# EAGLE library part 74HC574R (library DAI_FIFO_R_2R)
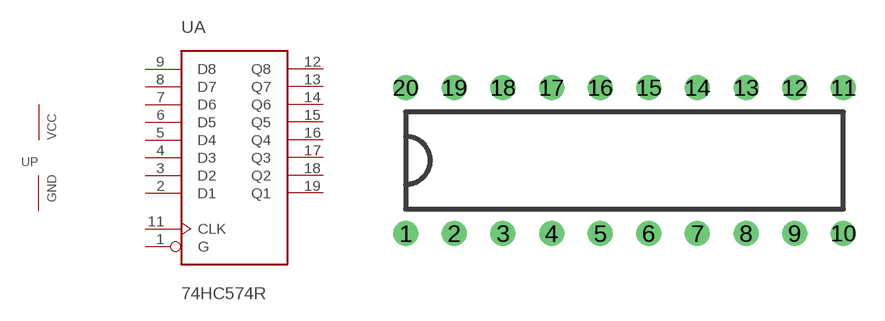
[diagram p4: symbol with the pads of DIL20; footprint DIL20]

Designator prefix U; gates P=DIP20_PWR A=74HC574R

## 74HC574R  [DIL20]
1  A:G  in
2  A:D1  in
3  A:D2  in
4  A:D3  in
5  A:D4  in
6  A:D5  in
7  A:D6  in
8  A:D7  in
9  A:D8  in
10  P:GND  pwr
11  A:CLK  in
12  A:Q8  hiz
13  A:Q7  hiz
14  A:Q6  hiz
15  A:Q5  hiz
16  A:Q4  hiz
17  A:Q3  hiz
18  A:Q2  hiz
19  A:Q1  hiz
20  P:VCC  pwr

## Footprint DIL20 (pad centres in mm)
drill 0.8 round: 1 -10.16,-2.54; 2 -7.62,-2.54; 3 -5.08,-2.54; 4 -2.54,-2.54; 5 0,-2.54; 6 2.54,-2.54; 7 5.08,-2.54; 8 7.62,-2.54; 9 10.16,-2.54; 10 12.7,-2.54; 11 12.7,5.08; 12 10.16,5.08; 13 7.62,5.08; 14 5.08,5.08; 15 2.54,5.08; 16 0,5.08; 17 -2.54,5.08; 18 -5.08,5.08; 19 -7.62,5.08; 20 -10.16,5.08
